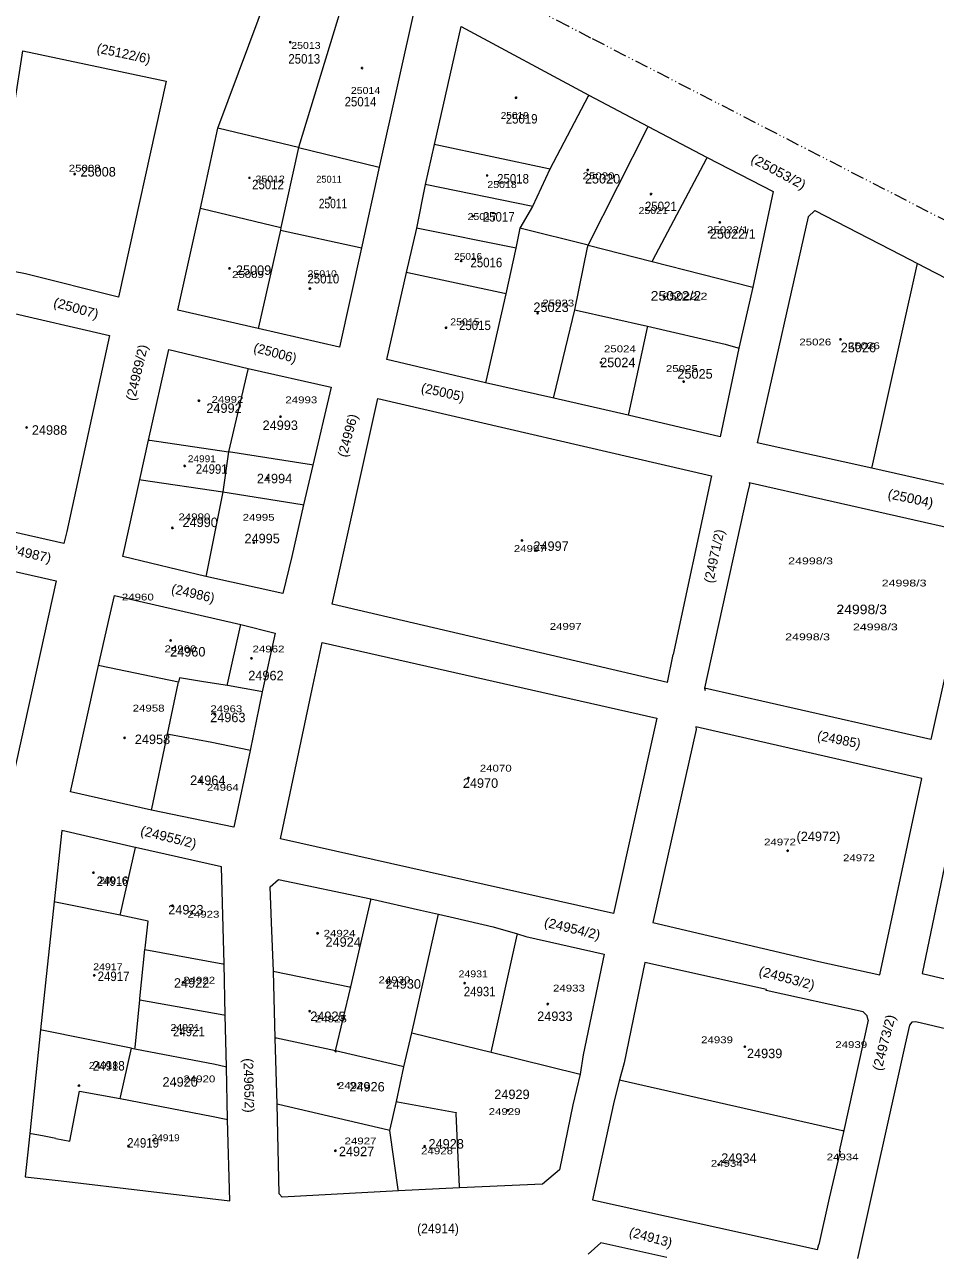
# Model space of a CAD drawing. Extents: x 649608 to 651081, y 237980 to 241202.
# Drawn here: x 649948.8 to 650294, y 240504.6 to 240969 of the extents above; entities that cross this region are included whole.
import ezdxf

# ---------------------------------------------------------------- set-up
doc = ezdxf.new("R2010")
doc.units = 0
doc.header["$PDMODE"] = 32
doc.header["$PDSIZE"] = 0.5
doc.linetypes.add('DASH_DOUBLE_DOT', pattern=[9.2, 5, -1.2, 0.3, -1.2, 0.3, -1.2])
for name, color, linetype in [('19', 7, 'Continuous'), ('20', 7, 'Continuous'), ('6', 7, 'Continuous')]:
    doc.layers.add(name, color=color, linetype=linetype)
for name, color, linetype, lineweight in [('3', 7, 'Continuous', 13), ('5', 7, 'Continuous', 13), ('52', 7, 'DASH_DOUBLE_DOT', 13), ('57', 7, 'Continuous', 13)]:
    doc.layers.add(name, color=color, linetype=linetype, lineweight=lineweight)

msp = doc.modelspace()

# ---------------------------------------------------------------- linework, layer by layer
at = {"layer": '3'}
for p, q in [((650046.735, 240753.463), (650017.549, 240759.932)), ((649982.946, 240752.751), (650030.792, 240741.653)), ((650192.382, 240719.782), (650194.534, 240730.324)), ((650042.446, 240628.866), (650041.9, 240642.334)), ((650268.436, 240591.808), (650259.226, 240549.977)), ((650257.882, 240542.17), (650253.698, 240524.35)), ((650253.698, 240524.35), (650249.799, 240506.856))]:
    msp.add_line(p, q, dxfattribs=at)
for points in [[(650037.393, 240853.814), (650006.927, 240860.813), (650015.54, 240899.38), (650022.04, 240929.739), (650049.084, 241002.219)], [(650049.084, 241002.219), (650073.193, 240989.986), (650097.11, 240977.37), (650083.194, 240914.969), (650076.491, 240884.412)], [(650104.097, 240923.539), (650114.206, 240968.205), (650162.589, 240942.273), (650185.127, 240930.313), (650207.515, 240918.602)], [(650123.436, 240833.227), (650086.089, 240842.039), (650093.587, 240875.024), (650097.488, 240891.839), (650100.759, 240908.409), (650104.097, 240923.539)], [(650207.515, 240918.602), (650232.487, 240905.705), (650224.769, 240869.542), (650219.52, 240846.377), (650212.397, 240812.793)], [(650248.288, 240898.496), (650245.682, 240896.121), (650226.422, 240810.518)], [(650248.288, 240898.496), (650280.841, 240881.776), (650287.174, 240878.478)], [(650076.491, 240884.412), (650068.16, 240846.763), (650037.393, 240853.814)], [(650287.174, 240878.478), (650293.731, 240875.063), (650326.436, 240858.215), (650327.368, 240855.592), (650312.463, 240791.324), (650269.845, 240800.921), (650226.422, 240810.518)], [(649995.809, 240811.558), (650003.44, 240845.834), (650033.502, 240838.738)], [(650033.502, 240838.738), (650065.049, 240831.582), (650058.076, 240802.071), (650054.462, 240787.068), (650050.141, 240767.474), (650046.735, 240753.463)], [(650212.397, 240812.793), (650177.512, 240820.992), (650149.306, 240827.453), (650123.436, 240833.227)], [(650192.382, 240719.782), (650065.322, 240749.406), (650082.704, 240827.283), (650209.086, 240798.012), (650194.534, 240730.324)], [(650017.549, 240759.932), (649986.105, 240767.509), (649992.548, 240796.627), (649995.809, 240811.558)], [(650223.417, 240795.43), (650223.553, 240794.729), (650222.676, 240791.083), (650206.497, 240717.549)], [(650223.417, 240795.43), (650307.133, 240776.57), (650308.295, 240775.78), (650309.204, 240774.353), (650308.746, 240772.419), (650292.209, 240698.101), (650206.497, 240717.549)], [(649996.932, 240671.346), (649966.265, 240678.273), (649976.796, 240726.19), (649981.059, 240744.468), (649982.946, 240752.751)], [(650030.792, 240741.653), (650043.75, 240738.481), (650038.884, 240716.183), (650034.282, 240693.989)], [(650203.164, 240702.971), (650203.288, 240701.967), (650186.906, 240628.881), (650249.73, 240614.021)], [(650249.73, 240614.021), (650272.937, 240609.022), (650288.775, 240683.344), (650203.164, 240702.971)], [(650034.282, 240693.989), (650028.123, 240664.933), (649996.932, 240671.346)], [(649990.806, 240657.195), (649990.758, 240657.206), (649962.905, 240663.715), (649960.072, 240636.658)], [(650024.416, 240613.121), (650023.435, 240649.918), (649990.806, 240657.195)], [(650041.9, 240642.334), (650045.086, 240645.068), (650080.086, 240637.789)], [(649960.072, 240636.658), (649956.739, 240605.953), (649954.869, 240588.156), (649950.879, 240548.836), (649948.993, 240532.529), (649962.716, 240531.015)], [(650080.086, 240637.789), (650098.885, 240633.503), (650105.694, 240631.948)], [(650105.694, 240631.948), (650111.69, 240630.608), (650126.374, 240627.226), (650135.611, 240624.492)], [(650090.513, 240527.22), (650046.433, 240524.728), (650045.233, 240526.028), (650044.487, 240559.967), (650043.736, 240585.062), (650043.112, 240610.33), (650042.446, 240628.866)], [(650135.611, 240624.492), (650138.782, 240623.503), (650168.377, 240616.845), (650160.501, 240578.713), (650159.324, 240571.393)], [(649962.716, 240531.015), (650026.554, 240523.355), (650025.688, 240554.164), (650025.308, 240574.114), (650024.825, 240593.717), (650024.416, 240613.121)], [(650268.436, 240591.808), (650268.096, 240593.47), (650266.555, 240594.96), (650229.866, 240603.083), (650229.949, 240603.485), (650183.851, 240613.615), (650175.975, 240575.696), (650174.288, 240569.201)], [(650367.209, 240562.582), (650368.783, 240569.636), (650368.608, 240571.167), (650367.259, 240572.096), (650286.579, 240591.249), (650284.955, 240591.124), (650284.131, 240589.969), (650282.457, 240582.689), (650264.467, 240501.506)], [(650159.324, 240571.393), (650156.586, 240559.738), (650151.48, 240535.156), (650145.133, 240529.737), (650145.184, 240529.786), (650145.133, 240529.762), (650113.559, 240528.298), (650090.513, 240527.22)], [(650174.288, 240569.201), (650172.265, 240561.315), (650163.985, 240523.715), (650249.284, 240504.971), (650249.799, 240506.856)], [(650259.226, 240549.977), (650257.429, 240542.266), (650257.882, 240542.17)], [(650192.146, 240501.902), (650167.155, 240507.496), (650162.349, 240503.208)]]:
    msp.add_lwpolyline(points, dxfattribs=at)
for points in [[(649984.472, 240865.644), (649949.238, 240874.49), (649935.422, 240877.247), (649948.175, 240959.032), (650002.431, 240947.466)], [(649963.751, 240772.414), (649920.651, 240782.136), (649931.296, 240852.609), (649931.915, 240855.114), (649933.387, 240857.24), (649935.862, 240858.812), (649935.887, 240858.811), (649938.131, 240859.789), (649941.756, 240860.26), (649981.062, 240851.161), (649964.785, 240776.903)], [(649918.324, 240767.869), (649960.797, 240758.3), (649944.236, 240683.1), (649906.134, 240691.619), (649917.099, 240760.848)], [(650061.56, 240734.826), (650188.373, 240706.276), (650171.912, 240632.238), (650045.847, 240660.528), (650057.754, 240717.216)], [(650373.055, 240589.718), (650388.724, 240661.431), (650303.719, 240680.522), (650288.878, 240609.549)]]:
    msp.add_lwpolyline(points, close=True, dxfattribs=at)
at = {"layer": '5'}
for p, q in [((650162.393, 240885.392), (650186.67, 240879.183)), ((650066.661, 240580.188), (650072.496, 240604.411)), ((649969.666, 240564.973), (649985.067, 240562.155)), ((649960.627, 240547.027), (649966.028, 240545.945))]:
    msp.add_line(p, q, dxfattribs=at)
for points in [[(650073.193, 240989.986), (650073.041, 240989.486), (650052.638, 240922.339), (650045.91, 240892.062), (650045.773, 240891.115)], [(650162.589, 240942.273), (650162.326, 240941.773), (650147.846, 240914.236), (650141.288, 240900.024), (650136.428, 240891.802), (650134.978, 240884.298), (650131.231, 240866.965)], [(650052.638, 240922.339), (650022.54, 240929.618), (650022.04, 240929.739)], [(650162.393, 240885.392), (650184.874, 240929.813), (650185.127, 240930.313)], [(650052.638, 240922.339), (650082.694, 240915.09), (650083.194, 240914.969)], [(650147.846, 240914.236), (650147.346, 240914.342), (650104.597, 240923.433), (650104.097, 240923.539)], [(650186.67, 240879.183), (650186.934, 240879.683), (650207.251, 240918.102), (650207.515, 240918.602)], [(650141.288, 240900.024), (650140.788, 240900.127), (650101.259, 240908.306), (650100.759, 240908.409)], [(650015.54, 240899.38), (650016.04, 240899.26), (650045.91, 240892.062)], [(650134.978, 240884.298), (650134.478, 240884.399), (650097.988, 240891.738), (650097.488, 240891.839)], [(650162.393, 240885.392), (650136.928, 240891.679), (650136.428, 240891.802)], [(650045.773, 240891.115), (650037.505, 240854.314), (650037.393, 240853.814)], [(650045.773, 240891.115), (650075.991, 240884.521), (650076.491, 240884.412)], [(650157.291, 240860.905), (650162.129, 240884.543), (650162.393, 240885.392)], [(650186.67, 240879.183), (650224.269, 240869.669), (650224.769, 240869.542)], [(650269.845, 240800.921), (650269.957, 240801.421), (650287.062, 240877.978), (650287.174, 240878.478)], [(650131.231, 240866.965), (650130.731, 240867.072), (650094.087, 240874.917), (650093.587, 240875.024)], [(650131.231, 240866.965), (650123.552, 240833.727), (650123.436, 240833.227)], [(650149.306, 240827.453), (650149.425, 240827.953), (650157.291, 240860.905)], [(650157.291, 240860.905), (650157.791, 240860.792), (650184.837, 240854.666)], [(650184.837, 240854.666), (650184.728, 240854.166), (650177.621, 240821.492), (650177.512, 240820.992)], [(650184.837, 240854.666), (650214.303, 240847.856), (650219.02, 240846.519), (650219.52, 240846.377)], [(650033.502, 240838.738), (650033.385, 240838.238), (650026.069, 240807.101), (650023.924, 240792.004)], [(649995.809, 240811.558), (649996.309, 240811.484), (650026.069, 240807.101)], [(650058.076, 240802.071), (650057.576, 240802.15), (650026.069, 240807.101)], [(649992.548, 240796.627), (649993.048, 240796.553), (650023.924, 240792.004)], [(650023.924, 240792.004), (650017.648, 240760.432), (650017.549, 240759.932)], [(650023.924, 240792.004), (650053.962, 240787.149), (650054.462, 240787.068)], [(650025.665, 240718.551), (650025.776, 240719.051), (650030.681, 240741.153), (650030.792, 240741.653)], [(650007.166, 240719.841), (649977.296, 240726.085), (649976.796, 240726.19)], [(650002.975, 240700.165), (650007.059, 240719.341), (650007.166, 240719.841)], [(650025.665, 240718.551), (650016.643, 240719.945), (650007.569, 240721.512), (650007.166, 240719.841)], [(650038.884, 240716.183), (650038.384, 240716.273), (650025.665, 240718.551)], [(649996.932, 240671.346), (649997.037, 240671.846), (650002.975, 240700.165)], [(650034.282, 240693.989), (650033.782, 240694.094), (650019.718, 240697.04), (650003.475, 240700.072), (650002.975, 240700.165)], [(649985.017, 240631.586), (649985.13, 240632.086), (649990.806, 240657.195)], [(649985.017, 240631.586), (649960.572, 240636.556), (649960.072, 240636.658)], [(650072.496, 240604.411), (650079.972, 240637.289), (650080.086, 240637.789)], [(649994.419, 240618.577), (649994.477, 240619.077), (649995.667, 240629.374), (649985.017, 240631.586)], [(650095.535, 240587.027), (650105.581, 240631.448), (650105.694, 240631.948)], [(650125.603, 240579.746), (650125.715, 240580.246), (650135.499, 240623.992), (650135.611, 240624.492)], [(649992.49, 240599.488), (649992.541, 240599.988), (649994.419, 240618.577)], [(649994.419, 240618.577), (650023.916, 240613.212), (650024.416, 240613.121)], [(650043.112, 240610.33), (650043.612, 240610.229), (650071.996, 240604.512), (650072.496, 240604.411)], [(649990.666, 240580.969), (649990.715, 240581.469), (649992.49, 240599.488)], [(649992.49, 240599.488), (650024.325, 240593.806), (650024.825, 240593.717)], [(649989.259, 240581.253), (649955.369, 240588.056), (649954.869, 240588.156)], [(650066.661, 240580.188), (650044.236, 240584.955), (650043.736, 240585.062)], [(650090.513, 240527.22), (650090.442, 240527.72), (650087.259, 240550.048), (650089.69, 240560.985), (650092.513, 240574.131), (650095.535, 240587.027)], [(650095.535, 240587.027), (650096.035, 240586.906), (650125.603, 240579.746)], [(649985.067, 240562.155), (649985.178, 240562.655), (649989.284, 240581.203), (649989.259, 240581.253)], [(649989.259, 240581.253), (649989.284, 240581.252), (649989.284, 240581.228), (649989.309, 240581.227), (649990.666, 240580.969)], [(649990.666, 240580.969), (650021.088, 240575.113), (650024.808, 240574.232), (650025.308, 240574.114)], [(650092.513, 240574.131), (650092.013, 240574.248), (650066.661, 240580.188)], [(650125.603, 240579.746), (650158.824, 240571.517), (650159.324, 240571.393)], [(650174.288, 240569.201), (650174.788, 240569.088), (650258.726, 240550.09), (650259.226, 240549.977)], [(649966.028, 240545.945), (649968.419, 240558.523), (649969.666, 240564.973)], [(649985.067, 240562.155), (650019.634, 240555.449), (650025.188, 240554.27), (650025.688, 240554.164)], [(650087.259, 240550.048), (650086.759, 240550.164), (650044.987, 240559.851), (650044.487, 240559.967)], [(650089.69, 240560.985), (650090.19, 240560.893), (650112.328, 240556.821), (650112.214, 240556.29), (650113.535, 240528.798), (650113.559, 240528.298)], [(649960.627, 240547.027), (649955.628, 240547.982), (649951.379, 240548.746), (649950.879, 240548.836)]]:
    msp.add_lwpolyline(points, dxfattribs=at)
at = {"layer": '52'}
msp.add_lwpolyline([(650605.404, 240765.589), (650560.735, 240764.555), (650550.489, 240764.279), (650545.807, 240764.444), (650545.649, 240764.537), (650532.911, 240771.119), (650350.609, 240867.503), (650336.954, 240874.591), (650323.91, 240881.206), (650163.407, 240963.863), (650154.776, 240968.319), (650055.166, 241019.937)], dxfattribs=at)
at = {"layer": '57'}
msp.add_line((650206.497, 240717.549), (650206.724, 240716.649), dxfattribs=at)
at = {"layer": '6'}
for p in [(650049.478, 240962.279), (650076.677, 240952.477), (650135.067, 240941.22), (649967.807, 240912.338), (650034.051, 240910.9), (650124.108, 240911.781), (650162.223, 240913.832), (650064.537, 240903.375), (650186.189, 240904.748), (650118.749, 240896.353), (650212.274, 240894.072), (650114.261, 240879.402), (650026.482, 240876.597), (650056.929, 240868.939), (650191.125, 240865.884), (650143.261, 240859.627), (650108.55, 240854.125), (650257.993, 240849.708), (650167.19, 240840.948), (650198.56, 240833.729), (650014.874, 240826.467), (650045.801, 240820.404), (649949.623, 240816.337), (650009.493, 240801.781), (650040.76, 240797.084), (650004.842, 240778.279), (650035.697, 240772.733), (650137.265, 240773.532), (650257.981, 240746.765), (650004.231, 240735.651), (650034.814, 240728.918), (650020.863, 240707.75), (649986.726, 240698.768), (650015.569, 240682.549), (650116.998, 240683.532), (650237.965, 240655.996), (649974.936, 240647.65), (650004.826, 240635.158), (650059.856, 240624.739), (649975.241, 240608.813), (650008.863, 240606.147), (650086.333, 240605.96), (650115.616, 240605.847), (650056.886, 240595.238), (650147.073, 240597.942), (650008.118, 240586.801), (650066.693, 240580.13), (650221.737, 240581.796), (649969.439, 240567.05), (650005.863, 240567.708), (650067.68, 240567.555), (650131.955, 240557.662), (649988.154, 240544.164), (650100.453, 240544.102), (650066.616, 240542.347), (650211.809, 240537.086)]:
    msp.add_point(p, dxfattribs=at)

# ---------------------------------------------------------------- texts
at = {"layer": '19'}
for s, rotation, p in [('(25122/6)', 347.966, (649975.95, 240958.381)), ('(25006)', 344.911, (650035.315, 240845.048)), ('(25005)', 347.192, (650098.829, 240829.787)), ('(24996)', 75.024, (650070.833, 240804.818)), ('(24971/2)', 77.873, (650209.697, 240757.145)), ('(24986)', 347.055, (650004.182, 240753.648)), ('(24985)', 348.708, (650248.95, 240698.006)), ('(24965/2)', 271.31, (650031.779, 240577.36)), ('(24913)', 344.697, (650177.622, 240510.05))]:
    msp.add_text(s, height=3.6, rotation=rotation, dxfattribs=at).set_placement(p)
for s, width, p in [('25013', 0.9, (650048.769, 240954.174)), ('25014', 0.9, (650070.085, 240937.951)), ('25019', 0.9, (650131.141, 240931.462)), ('25012', 0.9, (650035.041, 240906.586)), ('25018', 0.9, (650127.889, 240908.749)), ('25011', 0.8, (650060.33, 240899.376)), ('25021', 0.9, (650183.888, 240898.294)), ('25017', 0.9, (650122.471, 240894.329)), ('25016', 0.9, (650117.774, 240877.024)), ('25010', 0.9, (650055.995, 240870.895)), ('25022/2', 1.1, (650186.054, 240864.406)), ('25015', 0.9, (650113.438, 240853.23)), ('24991', 0.9, (650013.725, 240798.793)), ('24998/3', 1.1, (650256.438, 240745.627)), ('24916', 0.9, (649976.153, 240642.689)), ('24917', 0.9, (649976.514, 240606.638)), ('24931', 0.9, (650115.245, 240600.869)), ('24921', 0.9, (650005.055, 240585.728)), ('24918', 0.9, (649974.707, 240572.749)), ('24919', 0.9, (649987.714, 240543.548)), ('(24914)', 0.95, (650097.589, 240511.127))]:
    msp.add_text(s, height=3.6, dxfattribs=dict(at, width=width)).set_placement(p)
for s, rotation, width, p in [('(25053/2)', 331.855, 1.1, (650223.658, 240917.001)), ('(25007)', 344.185, 1.05, (649959.485, 240862.179)), ('(24989/2)', 76.826, 1.05, (649990.631, 240826.189)), ('(25004)', 348.039, 1.05, (650275.663, 240789.554)), ('(24987)', 347.356, 1.05, (649941.457, 240768.856)), ('(24955/2)', 345.981, 1.05, (649992.449, 240662.044)), ('(24954/2)', 346.4, 1.05, (650145.435, 240627.351)), ('(24953/2)', 344.899, 1.05, (650226.755, 240608.878)), ('(24973/2)', 75.657, 1.05, (650273.497, 240572.395))]:
    msp.add_text(s, height=3.6, rotation=rotation, dxfattribs=dict(at, width=width)).set_placement(p)
for s, p in [('25008', (649970.01, 240911.394)), ('25020', (650161.127, 240908.749)), ('25022/1', (650208.454, 240887.84)), ('25009', (650028.899, 240874.14)), ('25023', (650141.618, 240860.08)), ('25026', (650258.072, 240844.818)), ('25024', (650166.908, 240839.17)), ('25025', (650196.172, 240834.844)), ('24992', (650017.699, 240821.866)), ('24988', (649951.586, 240813.574)), ('24993', (650039.014, 240815.376)), ('24994', (650036.846, 240795.187)), ('24990', (650008.666, 240778.604)), ('24995', (650032.15, 240772.475)), ('24997', (650141.617, 240769.591)), ('24960', (650003.969, 240729.574)), ('24962', (650033.595, 240720.561)), ('24963', (650019.144, 240704.699)), ('24958', (649990.603, 240696.407)), ('24964', (650011.557, 240680.905)), ('24970', (650114.882, 240679.823)), ('(24972)', (650241.328, 240659.635)), ('24923', (650003.248, 240631.874)), ('24924', (650062.858, 240619.616)), ('24922', (650005.416, 240604.114)), ('24930', (650085.619, 240603.754)), ('24925', (650057.079, 240591.496)), ('24933', (650143.062, 240591.496)), ('24939', (650222.543, 240577.436)), ('24920', (650001.08, 240566.62)), ('24926', (650071.892, 240564.818)), ('24929', (650126.806, 240561.934)), ('24927', (650067.918, 240540.303)), ('24928', (650101.877, 240543.187)), ('24934', (650212.788, 240537.779))]:
    msp.add_text(s, height=3.6, dxfattribs=at).set_placement(p)
at = {"layer": '20'}
for s, width, p in [('25013', 1.15, (650049.871, 240959.742)), ('25014', 1.15, (650072.457, 240942.688)), ('25019', 1.1, (650129.223, 240933.227)), ('25008', 1.25, (649965.553, 240913.244)), ('25012', 1.15, (650036.321, 240909.156)), ('25020', 1.25, (650160.254, 240910.343)), ('25018', 1.15, (650124.171, 240907.048)), ('25017', 1.15, (650116.673, 240894.935)), ('25021', 1.15, (650181.467, 240897.212)), ('25022/1', 1.25, (650207.417, 240889.92)), ('25016', 1.1, (650111.583, 240879.828)), ('25009', 1.25, (650027.429, 240872.965)), ('25010', 1.15, (650056.057, 240873.277)), ('25023', 1.25, (650144.976, 240862.174)), ('25022/2', 1.35, (650190.594, 240864.767)), ('25015', 1.15, (650110.116, 240855.05)), ('25026', 1.25, (650242.379, 240847.409)), ('25024', 1.25, (650168.351, 240844.826)), ('25026', 1.25, (650260.816, 240846.001)), ('25025', 1.25, (650191.837, 240837.339)), ('24992', 1.25, (650019.653, 240825.645)), ('24993', 1.25, (650047.642, 240825.493)), ('24991', 1.1, (650010.682, 240803.182)), ('24990', 1.25, (650007.131, 240781.165)), ('24995', 1.25, (650031.466, 240780.999)), ('24997', 1.25, (650134.204, 240769.178)), ('24998/3', 1.35, (650238.165, 240764.49)), ('24998/3', 1.35, (650273.61, 240756.109)), ('24960', 1.25, (649985.689, 240750.81)), ('24997', 1.25, (650147.805, 240739.676)), ('24998/3', 1.35, (650237.029, 240735.729)), ('24998/3', 1.35, (650262.704, 240739.474)), ('24960', 1.25, (650001.872, 240731.188)), ('24962', 1.25, (650035.207, 240731.121)), ('24958', 1.25, (649989.779, 240708.721)), ('24963', 1.25, (650019.229, 240708.482)), ('24070', 1.25, (650121.313, 240685.976)), ('24964', 1.25, (650017.912, 240678.721)), ('24972', 1.25, (650229.014, 240658.011)), ('24972', 1.25, (650258.934, 240652.033)), ('24916', 1.1, (649977.126, 240643.477)), ('24923', 1.25, (650010.553, 240630.648)), ('24924', 1.25, (650062.136, 240623.435)), ('24917', 1.15, (649974.83, 240610.75)), ('24922', 1.25, (650008.958, 240605.659)), ('24930', 1.25, (650082.939, 240605.808)), ('24931', 1.15, (650113.257, 240608.058)), ('24933', 1.25, (650149.052, 240602.66)), ('24921', 1.15, (650004.094, 240587.77)), ('24925', 1.25, (650058.839, 240590.998)), ('24939', 1.25, (650205.158, 240583.09)), ('24939', 1.25, (650256.003, 240581.265)), ('24918', 1.15, (649973.191, 240573.357)), ('24920', 1.25, (650009.017, 240568.285)), ('24926', 1.25, (650067.542, 240565.775)), ('24929', 1.25, (650124.662, 240555.891)), ('24919', 1.1, (649996.955, 240545.987)), ('24927', 1.25, (650070.075, 240544.766)), ('24928', 1.25, (650099.08, 240541.035)), ('24934', 1.25, (650208.854, 240536.274)), ('24934', 1.25, (650252.744, 240538.704))]:
    msp.add_text(s, height=2.6, dxfattribs=dict(at, width=width)).set_placement(p)
msp.add_text('25011', height=2.6, dxfattribs=at).set_placement((650059.369, 240909.085))

doc.saveas('drawing.dxf')
